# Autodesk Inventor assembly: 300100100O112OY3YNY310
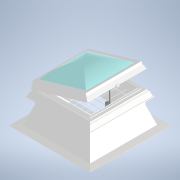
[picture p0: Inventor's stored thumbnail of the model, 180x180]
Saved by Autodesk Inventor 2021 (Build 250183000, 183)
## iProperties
Category: PARTsolutions
Company: KINGSPAN
Created: 2026-04
Part Number: 300100100O112OY3YNY310
Catalog Web Link: www.3dfindit.com
Description: LK neo plus-
Vendor: KINGSPAN
Document SubType Name: Assembly
Designer: psAdmin
Manufacturer: KINGSPAN
Mass: 209771 g
Surface Area: 114613 cm^2
Volume: 209771 cm^3
Density: 1 g/cm^3
Title: LKneoplus100100O112Y3YNY31
Author: Cadenas PARTsolutions
PSOL_IDENT_0: {$CADENAS_DATA/23d-libs/kingspan_kla/light_dome_classic_neoplus/light_dome_classic_neoplus_asmtab.pr
PSOL_IDENT_1: j},271 {VTYP=3D},{STYP=ASSTAB},{NB=300100100O112OY3YNY310},{LINA=LKneoplus100100O112Y3YNY31},{NN=LK
PSOL_IDENT_2: neo plus},{DATE=05.11.2025 13:48:11},{GEOMDATE=13.01.2025 13:06:59},{VERSION=},{LINEID=10},{WBVAR=LO
PSOL_IDENT_3: DLEVEL,L,W,TG,TS,DP,OP,OC,GCW,SD,IPM,EVADSS,SSSO,BA,INS,RT},{WBNUMERIC=W,RT}  {NB=300100100O112OY3YN
PSOL_IDENT_4: Y310},{LINA=LKneoplus100100O112Y3YNY31},{KT=DUMMY},{IDNR=},{PN=LK neo plus},{LODLEVEL=300},{L=100},{
PSOL_IDENT_5: W=100},{DRIVE=1},{WX=100,150,200,250,300},{TG=O},{TS=1},{WF=included},{DP=1},{OP=2},{OC=O},{SM=N},{G
PSOL_IDENT_6: CW=Y},{SD=3},{IPM=Y},{EVADSS=N},{SSSO=Y},{BA=3},{INS=1},{INSX='1','i - insulation','2','ih - enhance
PSOL_IDENT_7: d insulation'},{BAX='3', 'AK50 PVC' , '1', 'AK15 PVC','2', 'AK30 PVC' , '7' , 'AK30 AL/ST','8', 'AK4
PSOL_IDENT_8: 0 AL/ST', '9', 'AK50 AL/ST','13' , 'AK30 AL/AL', '14' , 'AK40 AL/AL', '15' , 'AK50 AL/AL', '16' , 'A
PSOL_IDENT_9: K50 ST-TG' , '10', 'AK30 ST', '11' , 'AK40 ST', '12', 'AK50 ST'},{UVD=1.2},{UVDU=calculated by excel
PSOL_IDENT_10: l tool},{LT=14},{GV=18},{SI=24},{WFX='Y','Yes','N','No'},{OPX='1','Manual with 300mm stroke','2','Li
PSOL_IDENT_11: near drive 300mm stroke 24V or 230V','3','Linear drive 500mm stroke 24V or 230V'},{TSX='1','PC-st 20
PSOL_IDENT_12: /7 + 1 shell','2','3‐shelled','3','3‐shelled with heat‐stop coating'},{LX=1000},{XWX=1000},{ANG=9.16
PSOL_IDENT_13: 37},{ROT=-16.367},{PPATH=parts/light_dome_classic_asmtpl.prj},{IBM=LKneoplus100100O112Y3YNY31},{SFX='
PSOL_IDENT_14: Y','Yes','N','No'},{DPX='3', 'Fixed','1', 'Natural ventilation'  ,'4','NSHE', '2', 'NSHEV'},{OCX='O'
PSOL_IDENT_15: , 'Open', 'C', 'Closed'},{SMX='N', 'No'},{VERPRA=1},{EVADSSX='N','No'},{RT=0},{SDX='1', 'RSM - round
PSOL_IDENT_16: bar fall-through protection mat', '2'  , 'EAD - laser cut fall-through protection mat', '3'  , 'HDS
PSOL_IDENT_17: - fall through/hale protection and shading system', '0'  , 'No Safety Device'}
NB: 300100100O112OY3YNY310
NN: LK neo plus
NBSYN: $LODLEVEL.$L.$W.$TG.$TS.$DP.$OP.$OC.$GCW.$SD.$IPM.$EVADSS.$SSSO.$BA.$INS.$RT.
LINA: LKneoplus100100O112Y3YNY31
CATALOG: Light + Air
PN: LK neo plus
LODLEVEL: 300
L: 100
W: 100
TG: opal
TS: PC-st 20/7 + 1 shell
WF: included
DP: Natural ventilation
OP: Linear drive 300mm stroke 24V or 230V
OC: Open
GCW: Yes
SD: HDS - fall through/hale protection and shading system
IPM: Yes
EVADSS: No
BA: AK PVC 50
INS: i - insulation
UVD: 1.2
LT: 14
GV: 18
SI: 24
RT: 0
SUPPLIER: KINGSPAN
ARTICLENO: 300100100O112OY3YNY310
BOMINFO: LKneoplus100100O112Y3YNY31
CREATOR: CADENAS GmbH
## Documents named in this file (12)
- e:\temp\worker_COMMON_221\temp\tmp_5860_6_gFUyQ\format_0\300100100O112OY3YNY310.iam
- e:\temp\worker_COMMON_221\temp\tmp_5860_6_gFUyQ\format_0\Light dome classic(30010010012320)_part_1_neoplus.ipt
- e:\temp\worker_COMMON_221\temp\tmp_5860_6_gFUyQ\format_0\Light dome classic(3001001003Y12O)_part_2_neoplus.ipt
- e:\temp\worker_COMMON_221\temp\tmp_5860_6_gFUyQ\format_0\Light dome classic(300100100)_part_8_neoplus.ipt
- e:\temp\worker_COMMON_221\temp\tmp_5860_6_gFUyQ\format_0\Light dome classic(30010010012)_part_9_neoplus.ipt
- e:\temp\worker_COMMON_221\temp\tmp_5860_6_gFUyQ\format_0\Light dome classic(30010010012O)_part_3_neoplus.ipt
- e:\temp\worker_COMMON_221\temp\tmp_5860_6_gFUyQ\format_0\Light dome classic(300100100O3)_part_4_neoplus.ipt
- e:\temp\worker_COMMON_221\temp\tmp_5860_6_gFUyQ\format_0\Light dome classic(300100100)_part_5_neoplus.ipt
- e:\temp\worker_COMMON_221\temp\tmp_5860_6_gFUyQ\format_0\Light dome classic(300100100)_part_6_neoplus.ipt
- e:\temp\worker_COMMON_221\temp\tmp_5860_6_gFUyQ\format_0\Light dome classic(30010010012)_part_11_neoplus.ipt
- e:\temp\worker_COMMON_221\temp\tmp_5860_6_gFUyQ\format_0\Light dome classic(300100100123O)_part_10_neoplus.ipt
- e:\temp\worker_COMMON_221\temp\tmp_5860_6_gFUyQ\format_0\Light dome classic(30010010012O3)_part_7_neoplus.ipt
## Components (12 placed, 11 different names)
1. Light dome classic(30010010012320)_part_1_neoplus:1
2. Light dome classic(3001001003Y12O)_part_2_neoplus:1
3. Light dome classic(300100100)_part_8_neoplus:1
4. Light dome classic(300100100)_part_8_neoplus:2
5. Light dome classic(30010010012)_part_9_neoplus:1
6. Light dome classic(30010010012O)_part_3_neoplus:1
7. Light dome classic(300100100O3)_part_4_neoplus:1
8. Light dome classic(300100100)_part_5_neoplus:1
9. Light dome classic(300100100)_part_6_neoplus:1
10. Light dome classic(30010010012)_part_11_neoplus:1
11. Light dome classic(300100100123O)_part_10_neoplus:1
12. Light dome classic(30010010012O3)_part_7_neoplus:1
